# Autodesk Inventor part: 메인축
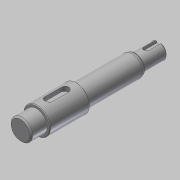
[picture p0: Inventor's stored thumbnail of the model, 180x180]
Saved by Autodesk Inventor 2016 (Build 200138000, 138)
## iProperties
Created: 2019-03
Part Number: 메인축
Material: 강철, 연강
Document SubType Name: Modeling
Designer: mduedu
Density: 1 g/cm^3
Appearance: 강철
Author: mduedu
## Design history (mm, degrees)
sketch "스케치1"
  geometry: L1 (0, 0)-(12, 0); L2 (12, 0)-(12, 8); L3 (12, 8)-(0, 8); L4 (0, 8)-(0, 0); L5 (12, 0)-(42, 0); L6 (42, 0)-(42, 10); L7 (42, 10)-(12, 10); L8 (12, 10)-(12, 0); L9 (42, 0)-(86, 0); L10 (86, 0)-(86, 8); L11 (86, 8)-(42, 8); L12 (42, 8)-(42, 0); L13 (86, 0)-(104, 0); L14 (104, 0)-(104, 6); L15 (104, 6)-(86, 6); L16 (86, 6)-(86, 0)
  constraints: 32 end point, 8 parallel, 4 horizontal, 4 perpendicular
  dimensions: "d0" = 16 diameter of L3 L1; "d2" = 20 diameter of L7 L5; "d3" = 16 diameter of L11 L9; "d4" = 12 diameter of L15 L13; "d5" = 12 distance of L2.end L3.end; "d6" = 30 distance of L6.end L7.end; "d7" = 86 distance between parallel lines of L10 L4; "d8" = 104 distance between parallel lines of L14 L4
revolve "회전1" sketch "스케치1" stored, may be unused: angle "d9" = 90 deg
node "작업 평면1"
sketch "스케치2" dims "d10" = 18
  geometry: L1 (6, -3)-(-6, -3); L2 (-6, -3)-(-6, 3); L3 (-6, 3)-(6, 3); L4 (6, 3)-(6, -3); L5 (15, 10)-(15, -10) reference; 3 further points
  constraints: 8 end point, 2 midpoint, 2 parallel, 2 vertical alignment, 1 horizontal, 1 horizontal alignment, 1 perpendicular, 4 other
  dimensions: "d12" = 6 distance between parallel lines of L3 L1; "d13" = 6 dimension on L5
extrude "돌출1" cut sketch "스케치2" distance "d14" = 3.5; taper "d15" = 0 deg
node "작업 평면2"
sketch "스케치3"
  geometry: L1 (-9, 6)-(-9, -6) reference; L2 (1, -2)-(-9, -2); L3 (1, 2)-(-9, 2); A1 r 2 centre (1, 0) between (1, -2) and (1, 2); 2 further points
  constraints: 4 end point, 2 point on circle, 2 point on line, 2 tangent, 1 centre point, 1 horizontal alignment, 1 midpoint, 1 parallel, 1 perpendicular
  dimensions: "d16" = 12 dimension on A1 L1; "d17" = 4 distance between parallel lines of L3 L2
extrude "돌출2" cut sketch "스케치3" distance "d18" = 2.5; taper "d19" = 0 deg
chamfer "모따기1" distance "d20" = 1; stored, may be unused: second distance "d21" = 2, angle "d22" = 45 deg
chamfer "모따기2" distance "d23" = 0.5; stored, may be unused: second distance "d24" = 2, angle "d25" = 45 deg
chamfer "모따기3" distance "d26" = 1.73; stored, may be unused: second distance "d27" = 2, angle "d28" = 30 deg
fillet "모깎기2" dims "d31" = 0.5, "d32" = 4
node "솔리드1"
